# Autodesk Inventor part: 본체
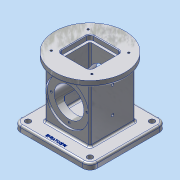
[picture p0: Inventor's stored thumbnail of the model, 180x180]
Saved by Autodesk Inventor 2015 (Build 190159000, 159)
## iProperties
Created: 2021-05
Part Number: 본체
Material: 알루미늄 6061
Document SubType Name: Modeling
Designer: 102879
Density: 2.7 g/cm^3
Appearance: 알루미늄 - 평지
Mass: 1250.85 g
Surface Area: 897.095 cm^2
Volume: 463.277 cm^3
Author: 102879
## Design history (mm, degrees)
sketch "스케치1"
  geometry: L1 (37, -37)-(-37, -37); L2 (-37, -37)-(-37, 37); L3 (-37, 37)-(37, 37); L4 (37, 37)-(37, -37); L5 (37, -37)-(-37, 37); L6 (-37, -37)-(37, 37); 1 further point
  constraints: 12 end point, 2 midpoint, 2 parallel, 1 horizontal, 1 perpendicular
  dimensions: "d0" = 74 distance of L2.end L3.end; "d1" = 74 distance of L1.end L2.end
extrude "돌출1" new body sketch "스케치1" stored distance "d2" = 88; taper "d3" = 0 deg
sketch "스케치2"
  geometry: C1 r 57.5 at (0, 0); 1 further point
  constraints: 1 centre point, 1 coincident
  dimensions: "d4" = 115 diameter of C1
extrude "돌출2" join sketch "스케치2" distance "d5" = 10; taper "d6" = 0 deg
sketch "스케치3"
  geometry: L1 (-62.5, 62.5)-(62.5, 62.5); L2 (62.5, 62.5)-(62.5, -62.5); L3 (62.5, -62.5)-(-62.5, -62.5); L4 (-62.5, -62.5)-(-62.5, 62.5); L5 (-62.5, 62.5)-(62.5, -62.5); L6 (62.5, 62.5)-(-62.5, -62.5); 1 further point
  constraints: 12 end point, 2 midpoint, 2 parallel, 1 horizontal, 1 perpendicular
  dimensions: "d7" = 125 distance of L2.end L3.end; "d8" = 125 distance of L1.end L2.end
extrude "돌출3" join sketch "스케치3" distance "d9" = 10; taper "d10" = 0 deg
sketch "스케치4"
  geometry: L1 (44, 37)-(-44, 37) reference; L2 (0, 37)-(35, 37); L3 (35, 37)-(35, 34); L4 (35, 34)-(0, 34); L5 (0, 34)-(0, 37); L6 (0, 34)-(24, 34); L7 (24, 34)-(24, -34); L8 (24, -34)-(0, -34); L9 (0, -34)-(0, 34); L10 (-44, -37)-(44, -37) reference; L11 (0, -34)-(35, -34); L12 (35, -34)-(35, -37); L13 (35, -37)-(0, -37); L14 (0, -37)-(0, -34); 1 further point
  constraints: 24 end point, 6 parallel, 3 horizontal, 3 perpendicular, 2 point on line, 1 midpoint
  dimensions: "d11" = 70 diameter of L3 L9; "d12" = 48 diameter of L7 L9; "d13" = 3 distance between parallel lines of L1 L4; "d14" = 3 distance between parallel lines of L10 L8
revolve "회전1" sketch "스케치4" stored, may be unused: angle "d15" = 90 deg
sketch "스케치5" dims "d16" = 58
  geometry: C1 r 24 at (0, 0) reference; C2 r 35 at (0, 0) reference; 2 further points
  constraints: 2 vertical alignment, 1 coincident, 2 other
hole "구멍1" sketch "스케치5" at (0, 29) diameter "d17" = 3.242; stored, may be unused: countersink angle "d21" = 90 deg, drill point angle "d23" = 118 deg; dims "d18" = 8, "d19" = 4, "d20" = 2, "d22" = 10
sketch "스케치6"
  geometry: L1 (-22, -22)-(22, -22); L2 (22, -22)-(22, 22); L3 (22, 22)-(-22, 22); L4 (-22, 22)-(-22, -22); L5 (-22, -22)-(22, 22); L6 (22, -22)-(-22, 22); C1 r 57.5 at (0, 0) reference
  constraints: 12 end point, 2 midpoint, 2 parallel, 1 horizontal, 1 perpendicular
  dimensions: "d27" = 44 distance of L3.end L2.end; "d28" = 44 distance of L2.end L1.end
extrude "돌출4" cut sketch "스케치6" distance "d29" = 82; taper "d30" = 0 deg
sketch "스케치7"
  geometry: L1 (22, 22)-(22, -22) reference; L2 (22, -22)-(-22, -22) reference; L3 (-22, -22)-(-22, 22) reference; L4 (-22, 22)-(22, 22) reference; L5 (-26, -26)-(26, -26); L6 (26, -26)-(26, 26); L7 (26, 26)-(-26, 26); L8 (-26, 26)-(-26, -26); L9 (-26, -26)-(26, 26); L10 (26, -26)-(-26, 26); C1 r 57.5 at (0, 0) reference
  constraints: 12 end point, 2 midpoint, 2 parallel, 1 horizontal, 1 perpendicular
  dimensions: "d31" = 52 distance of L7.end L6.end; "d32" = 52 distance of L6.end L5.end
extrude "돌출5" cut sketch "스케치7" distance "d33" = 8; taper "d34" = 0 deg
fillet "모깎기1" dims "d35" = 3
fillet "모깎기2" dims "d36" = 3
fillet "모깎기3" dims "d37" = 6
chamfer "모따기1" distance "d38" = 1; stored, may be unused: second distance "d39" = 2, angle "d40" = 45 deg
fillet "모깎기4" dims "d41" = 3
fillet "모깎기5" dims "d42" = 3
fillet "모깎기6" dims "d43" = 12
sketch "스케치8"
  geometry: A1 r 12 centre (-50.5, -50.5) between (-62.5, -50.5) and (-50.5, -62.5) reference; A2 r 12 centre (50.5, -50.5) between (50.5, -62.5) and (62.5, -50.5) reference; A3 r 12 centre (50.5, 50.5) between (62.5, 50.5) and (50.5, 62.5) reference; A4 r 12 centre (-50.5, 50.5) between (-50.5, 62.5) and (-62.5, 50.5) reference; 1 further point
hole "구멍2" sketch "스케치8" at (-50.5, 50.5), (50.5, 50.5), (-50.5, -50.5), (50.5, -50.5) diameter "d44" = 9; stored, may be unused: countersink angle "d48" = 90 deg, drill point angle "d50" = 118 deg; dims "d45" = 8, "d46" = 4, "d47" = 2, "d49" = 10
sketch "스케치9"
  geometry: L1 (33, 30)-(-33, 30); L2 (-33, 30)-(-33, -30); L3 (-33, -30)-(33, -30); L4 (33, -30)-(33, 30); L5 (33, 30)-(-33, -30); L6 (-33, 30)-(33, -30); C1 r 57.5 at (0, 0) reference; 4 further points
  constraints: 12 end point, 4 coincident, 2 midpoint, 2 parallel, 1 horizontal, 1 perpendicular
  dimensions: "d51" = 66 distance of L3.end L2.end; "d52" = 60 distance of L2.end L1.end
hole "구멍3" sketch "스케치9" at (33, 30), (-33, 30), (33, -30), (-33, -30) diameter "d53" = 3.242; stored, may be unused: countersink angle "d57" = 90 deg, drill point angle "d59" = 118 deg; dims "d54" = 8, "d55" = 4, "d56" = 2, "d58" = 10
sketch "스케치10"
  geometry: L1 (84.5, -13)-(-16.5, -13) reference; 2 further points
  constraints: 1 vertical alignment
  dimensions: "d60" = 37 distance from line of L1 point (34, 24)
hole "구멍4" sketch "스케치10" at (34, 24) diameter "d62" = 4.134; stored, may be unused: countersink angle "d66" = 90 deg, drill point angle "d68" = 0 deg; dims "d63" = 10, "d64" = 4, "d65" = 2, "d67" = 14.2
sketch "스케치11"
  geometry: C1 r 2.067 at (34, 24) reference; 2 further points
  constraints: 1 vertical alignment
  dimensions: "d69" = 43 distance of C1.centre point (34, 67)
hole "구멍5" sketch "스케치11" at (34, 67) diameter "d70" = 4.134; stored, may be unused: countersink angle "d74" = 90 deg, drill point angle "d76" = 0 deg; dims "d71" = 10, "d72" = 4, "d73" = 2, "d75" = 14.2
sketch "스케치12"
  geometry: L1 (-54, -50.5)-(-54, 50.5) reference; L2 (-54, 0)-(-36, 0); L3 (-36, 0)-(-36, 24.826); L4 (-36, 24.826)-(-54, 28); L5 (-54, 0)-(-54, 28); 1 further point
  constraints: 8 end point, 1 horizontal, 1 midpoint, 1 parallel, 1 point on line, 1 vertical
  dimensions: "d77" = 18 distance of L2.start L2.end; "d78" = 80 deg angle of L1 L4; "d79" = 56 diameter of L4.end L2
revolve "회전2" sketch "스케치12" stored, may be unused: angle "d80" = 90 deg
fillet "모깎기7" dims "d81" = 3
node "작업 평면1"
sketch "스케치13"
  geometry: 2 further points
  constraints: 1 vertical alignment, 1 other
  dimensions: "d83" = 55 distance of point (0, 0) point (0, -55)
feature "엠보싱1" sketch "스케치13" dims "d0" = 74, "d1" = 74, "d84" = 0.5, "d85" = 0
fillet "모깎기8" dims "d86" = 3
node "솔리드1"
pattern_circular "원형 패턴1" dims angle "d25" = 360 deg
mirror "대칭1"
other parameters: "d82" = 5
